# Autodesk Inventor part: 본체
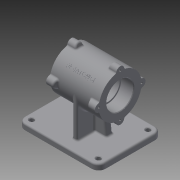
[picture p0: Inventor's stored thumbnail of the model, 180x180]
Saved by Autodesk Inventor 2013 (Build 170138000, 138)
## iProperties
Created: 2015-12
Part Number: 본체
Material: 일반
Document SubType Name: Modeling
Designer: a
Density: 1 g/cm^3
Author: a
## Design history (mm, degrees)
sketch "스케치1"
  geometry: L1 (-58.819, 55)-(60, 55); L2 (60, 55)-(60, -55); L3 (60, -55)-(-58.819, -55); L4 (-58.819, -55)-(-80, -55); L5 (-80, -55)-(-80, 55); L6 (-80, 55)-(-58.819, 55); 2 further points
  constraints: 12 end point, 3 parallel, 1 collinear, 1 horizontal, 1 horizontal alignment, 1 midpoint, 1 perpendicular
  dimensions: "d1" = 80 distance from line of L5 point (0, 0); "d2" = 140 distance between parallel lines of L2 L5; "d3" = 55 distance from line of L1 point (0, 0)
extrude "돌출1" new body sketch "스케치1" distance "d4" = 10; taper "d5" = 0 deg
sketch "스케치2"
  geometry: L1 (55, 10)-(55, 0) reference; L2 (55, 0)-(-55, 0) reference; L3 (-55, 0)-(-55, 10) reference; L4 (-55, 10)-(55, 10) reference; C1 r 37 at (0, 80); 2 further points
  constraints: 1 centre point, 1 midpoint, 1 vertical alignment
  dimensions: "d6" = 74 diameter of C1; "d8" = 80 distance from line of L2 C1.centre
extrude "돌출2" join sketch "스케치2" stored distance "d9" = 85; taper "d10" = 0 deg
sketch "스케치3"
  geometry: L1 (-4, 37)-(4, 37); L2 (4, 37)-(4, -37); L3 (4, -37)-(-4, -37); L4 (-4, -37)-(-4, 37); 3 further points
  constraints: 8 end point, 2 midpoint, 2 parallel, 1 horizontal, 1 horizontal alignment, 1 perpendicular, 1 vertical alignment
  dimensions: "d11" = 8 distance between parallel lines of L4 L2; "d13" = 37 vertical distance of L1.end point (0, 0)
extrude "돌출3" join sketch "스케치3" distance "d14" = 70; taper "d15" = 0 deg
sketch "스케치4"
  geometry: L1 (80, 10)-(80, 0) reference; L2 (80, 0)-(-60, 0) reference; L3 (-60, 0)-(-60, 10) reference; L4 (-60, 10)-(-4, 10) reference; L5 (-4, 10)-(-4, 43) reference; L6 (-4, 43)-(-42.5, 43) reference; L7 (-42.5, 43)-(-42.5, 117) reference; L8 (-42.5, 117)-(42.5, 117) reference; L9 (42.5, 117)-(42.5, 43) reference; L10 (42.5, 43)-(4, 43) reference; L11 (4, 43)-(4, 10) reference; L12 (4, 10)-(80, 10) reference; L13 (15.177, 80)-(25, 0); L14 (25, 0)-(0, 0); L15 (0, 0)-(0, 80); L16 (0, 80)-(15.177, 80); L17 (-42.5, 80)-(60.687, 80)
  constraints: 10 end point, 3 collinear, 1 midpoint, 1 parallel, 1 perpendicular
  dimensions: "d16" = 25 distance of L13.end L14.end; "d17" = 97 deg angle of L13 L14
extrude "돌출4" join sketch "스케치4" stored distance "d18" = 12; taper "d19" = 0 deg
hole "구멍1" diameter "d22" = 42; stored, may be unused: countersink angle "d26" = 90 deg, drill point angle "d28" = 118 deg; dims "d20" = 10, "d21" = 10, "d23" = 6, "d24" = 47, "d25" = 22, "d27" = 8
sketch "스케치5"
  geometry: C1 r 21 at (0, 0) reference; C2 r 37 at (0, 0) reference; C3 r 23.5 at (0, 0); 1 further point
  constraints: 1 centre point, 1 coincident
  dimensions: "d29" = 47 diameter of C3
extrude "돌출5" cut sketch "스케치5" distance "d31" = 22; taper "d32" = 0 deg
fillet "모깎기1" dims "d40" = 12
hole "구멍2" diameter "d43" = 8; stored, may be unused: countersink angle "d47" = 90 deg, drill point angle "d49" = 0 deg; dims "d44" = 6, "d45" = 47, "d46" = 22, "d48" = 10, "d95" = 10, "d96" = 10
fillet "모깎기2" dims "d56" = 3
fillet "모깎기3" dims "d57" = 3
fillet "모깎기4" dims "d58" = 3
fillet "모깎기5" dims "d59" = 3
node "작업 평면2"
  node "작업 평면1"
sketch "스케치7"
  geometry: L1 (-42.5, 37)-(42.5, 37) reference; L2 (-42.5, 37)-(-42.5, -37) reference; 3 further points
  constraints: 1 horizontal alignment, 1 midpoint, 1 other
  dimensions: "d62" = 42.5 distance from line of L2 point (0, 0)
feature "엠보싱1" sketch "스케치7" dims "d1" = 80, "d2" = 140, "d3" = 55, "d11" = 8, "d13" = 37, "d63" = 0.5, "d64" = 0
sketch "스케치9"
  geometry: C1 r 23.5 at (0, 0) reference; C2 r 7 at (-37, 0); 2 further points
  constraints: 2 horizontal alignment, 1 centre point, 1 other
  dimensions: "d67" = 7 radius of C2
extrude "돌출7" join sketch "스케치9" distance "d69" = 15; taper "d70" = 0 deg
hole "구멍3" diameter "d73" = 3.242; stored, may be unused: countersink angle "d77" = 90 deg, drill point angle "d79" = 118 deg; dims "d71" = 10, "d72" = 10, "d74" = 9, "d75" = 47, "d76" = 22, "d78" = 11
chamfer "모따기1" distance "d85" = 1; stored, may be unused: second distance "d86" = 2, angle "d87" = 45 deg
fillet "모깎기6" dims "d88" = 0.3
sketch "스케치11"
  geometry: L1 (-30.526, 117)-(-31.5, 118.621) reference; L2 (-31.5, 118.621)-(-42.5, 118.621) reference; L3 (-42.5, 118.621)-(-42.5, 124) reference; L4 (-42.5, 124)-(-27.5, 124) reference; L5 (-27.5, 124)-(-27.5, 117) reference; L6 (-27.5, 117)-(27.5, 117) reference; L7 (27.5, 117)-(27.5, 124) reference; L8 (27.5, 124)-(42.5, 124) reference; L9 (42.5, 124)-(42.5, 118.621) reference; L10 (42.5, 118.621)-(31.5, 118.621) reference; L11 (31.5, 118.621)-(30.526, 117) reference; L12 (30.526, 117)-(31.5, 115.379) reference; L13 (31.5, 115.379)-(42.5, 115.379) reference; L14 (42.5, 115.379)-(42.5, 104.5) reference; L15 (42.5, 104.5)-(41.5, 103.5) reference; L16 (41.5, 103.5)-(20.8, 103.5) reference; L17 (20.5, 103.2)-(20.5, 101) reference; L18 (20.5, 101)-(-20.5, 101) reference; L19 (-20.5, 101)-(-20.5, 103.2) reference; L20 (-20.8, 103.5)-(-41.5, 103.5) reference; L21 (-41.5, 103.5)-(-42.5, 104.5) reference; L22 (-42.5, 104.5)-(-42.5, 115.379) reference; L23 (-42.5, 115.379)-(-31.5, 115.379) reference; L24 (-31.5, 115.379)-(-30.526, 117) reference; L25 (26.426, 10)-(77, 10) reference; L26 (80, 7)-(80, 0) reference; L27 (80, 0)-(-60, 0) reference; L28 (-60, 0)-(-60, 7) reference; L29 (-57, 10)-(-26.426, 10) reference; L30 (-23.449, 12.634)-(-20.134, 39.634) reference; L31 (-23.111, 43)-(-27.5, 43) reference; L32 (-27.5, 43)-(-27.5, 36) reference; L33 (-27.5, 36)-(-42.5, 36) reference; L34 (-42.5, 36)-(-42.5, 41.379) reference; L35 (-42.5, 41.379)-(-31.5, 41.379) reference; L36 (-31.5, 41.379)-(-30.526, 43) reference; L37 (-30.526, 43)-(-31.5, 44.621) reference; L38 (-31.5, 44.621)-(-42.5, 44.621) reference; L39 (-42.5, 44.621)-(-42.5, 55.5) reference; L40 (-42.5, 55.5)-(-41.5, 56.5) reference; L41 (-41.5, 56.5)-(-20.8, 56.5) reference; L42 (-20.5, 56.8)-(-20.5, 59) reference; L43 (-20.5, 59)-(20.5, 59) reference; L44 (20.5, 59)-(20.5, 56.8) reference; L45 (20.8, 56.5)-(41.5, 56.5) reference; L46 (41.5, 56.5)-(42.5, 55.5) reference; L47 (42.5, 55.5)-(42.5, 44.621) reference; L48 (42.5, 44.621)-(31.5, 44.621) reference; L49 (31.5, 44.621)-(30.526, 43) reference; L50 (30.526, 43)-(31.5, 41.379) reference; L51 (31.5, 41.379)-(42.5, 41.379) reference; L52 (42.5, 41.379)-(42.5, 36) reference; L53 (42.5, 36)-(27.5, 36) reference; L54 (27.5, 36)-(27.5, 43) reference; L55 (27.5, 43)-(23.111, 43) reference; L56 (20.134, 39.634)-(23.449, 12.634) reference; L57 (27.5, 117)-(30.048, 124); L58 (37.937, 117)-(27.5, 117); L59 (30.048, 124)-(26.426, 124); L60 (27.5, 117)-(26.426, 117); L61 (0, 80)-(47.406, 80); L62 (26.426, 117)-(26.426, 124); A1 r 0.3 centre (20.8, 103.2) between (20.8, 103.5) and (20.5, 103.2) reference; A2 r 0.3 centre (-20.8, 103.2) between (-20.5, 103.2) and (-20.8, 103.5) reference; A3 r 3 centre (26.426, 13) between (23.449, 12.634) and (26.426, 10) reference; A4 r 3 centre (77, 7) between (80, 7) and (77, 10) reference; A5 r 3 centre (-57, 7) between (-57, 10) and (-60, 7) reference; A6 r 3 centre (-26.426, 13) between (-26.426, 10) and (-23.449, 12.634) reference; A7 r 0.3 centre (-20.8, 56.8) between (-20.8, 56.5) and (-20.5, 56.8) reference; A8 r 0.3 centre (20.8, 56.8) between (20.5, 56.8) and (20.8, 56.5) reference; 1 further point
  constraints: 12 end point, 3 collinear, 1 perpendicular, 1 point on line, 1 vertical alignment, 2 other
  dimensions: "d89" = 110 deg angle of L57 L58; "d90" = 15 distance from line of L57.start L9; "d91" = 80 distance between parallel lines of L27 L61
  node "절단 모서리 투영5"
revolve "회전1" stored, may be unused: angle "d92" = 90 deg
fillet "모깎기7" dims "d93" = 3
fillet "모깎기8" dims "d94" = 3
chamfer "모따기2" distance "d97" = 1; stored, may be unused: second distance "d98" = 2, angle "d99" = 45 deg
node "솔리드1"
mirror "대칭1"
pattern_linear "직사각형 패턴1" dims "d52" = 116, "d55" = 86
pattern_circular "원형 패턴2" dims angle "d83" = 360 deg
mirror "대칭2"
mirror "대칭3"
node "작업축1"
node "절단 모서리 투영1"
node "절단 모서리 투영2"
other parameters: "d60" = -45 deg, "d61" = -37.5
